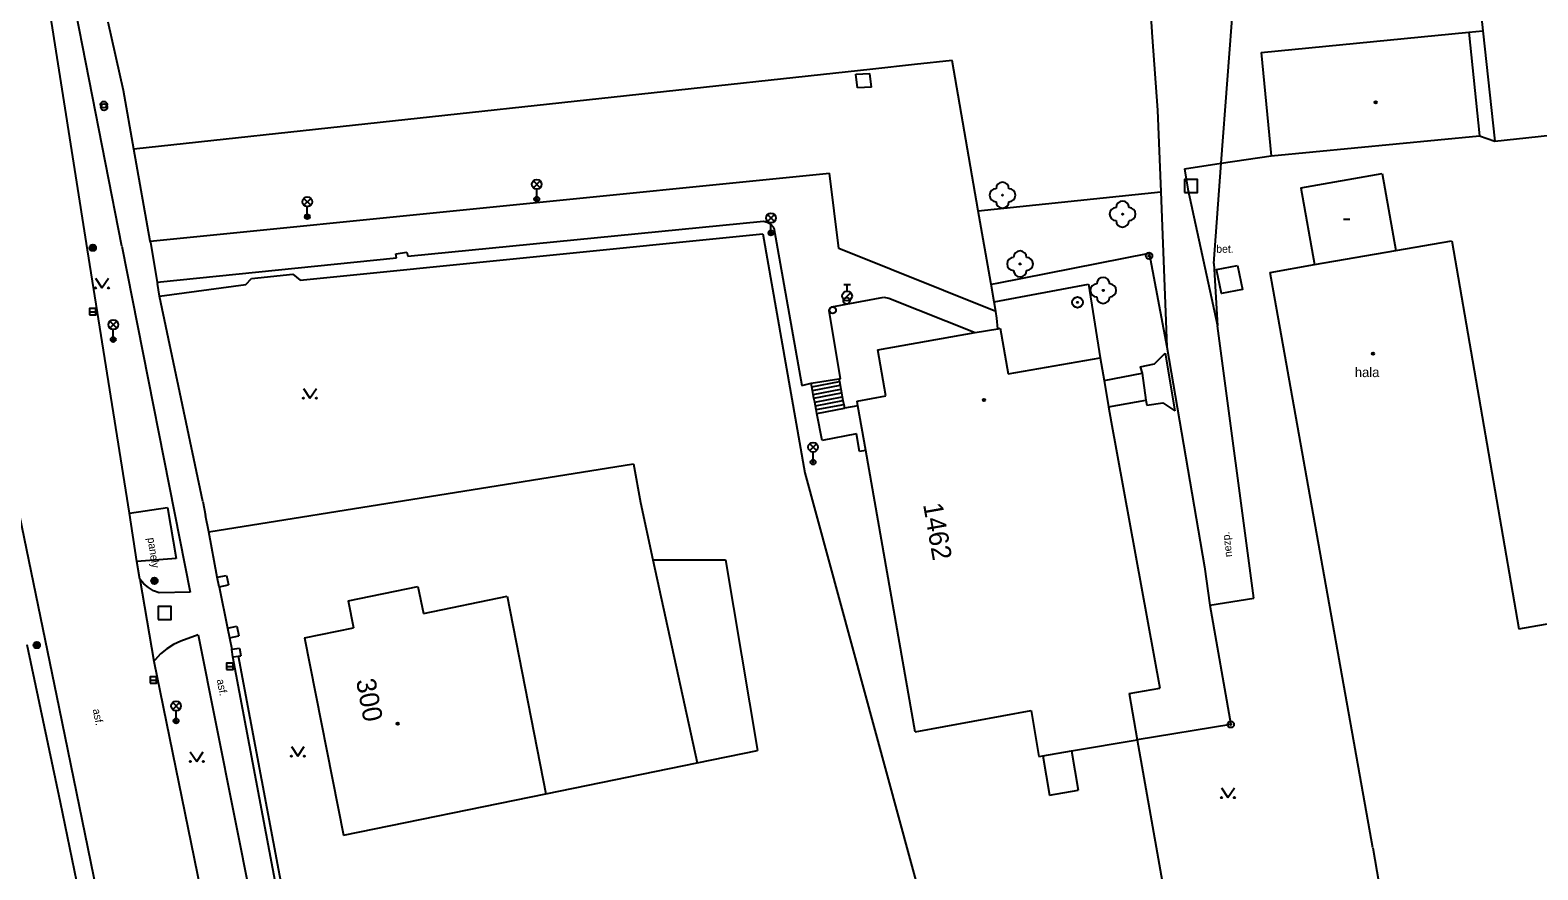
# Model space of a CAD drawing. Extents: x -640201 to -639641, y -1044739 to -1044317.
# Drawn here: x -640104 to -639987.9, y -1044553.8 to -1044489 of the extents above; entities that cross this region are included whole.
import ezdxf

# ---------------------------------------------------------------- set-up
doc = ezdxf.new("R2010")
doc.units = 0
for name, color, linetype in [('Budovy', 7, 'Continuous'), ('Ploty', 7, 'Continuous'), ('Pol_bod_pole', 7, 'Continuous'), ('Popis objektů', 7, 'Continuous'), ('Popis povrchů', 7, 'Continuous'), ('Popis ČP_ ČE', 7, 'Continuous'), ('Rozhraní ploch 1', 7, 'Continuous'), ('Rozhraní ploch 2', 7, 'Continuous'), ('Sloupy_označník', 7, 'Continuous'), ('Vstup na pozemky', 7, 'Continuous'), ('Zeleň - stromy', 7, 'Continuous'), ('Znaky doprava', 7, 'Continuous'), ('Znaky kanalizace', 7, 'Continuous'), ('Znaky voda', 7, 'Continuous'), ('Značky KM', 7, 'Continuous'), ('Značky předmětů', 7, 'Continuous'), ('Šachty ner_', 7, 'Continuous')]:
    doc.layers.add(name, color=color, linetype=linetype)

msp = doc.modelspace()

# ---------------------------------------------------------------- linework, layer by layer
at = {"layer": 'Budovy'}
for p, q in [((-639993.46, -1044476.5), (-639992.1, -1044489.08)), ((-639992.1, -1044489.08), (-639991.18, -1044497.58)), ((-640009.17, -1044490.73), (-640008.41, -1044498.7)), ((-639991.18, -1044497.58), (-639972.81, -1044495.6)), ((-640008.41, -1044498.7), (-639992.37, -1044497.17)), ((-639998.802, -1044506.013), (-639994.48, -1044505.27)), ((-639994.48, -1044505.27), (-639989.34, -1044535.18)), ((-640005.07, -1044507.09), (-639998.802, -1044506.013)), ((-640008.48, -1044507.7), (-640005.07, -1044507.09)), ((-640000.58, -1044552.05), (-640008.48, -1044507.7)), ((-640038.72, -1044513.66), (-640031.213, -1044512.337)), ((-640031.213, -1044512.337), (-640029.48, -1044512.032)), ((-640029.48, -1044512.032), (-640029.3, -1044512)), ((-640029.3, -1044512), (-640028.681, -1044515.512)), ((-640038.1, -1044517.21), (-640038.72, -1044513.66)), ((-640028.681, -1044515.512), (-640021.59, -1044514.29)), ((-640021.59, -1044514.29), (-640021.289, -1044516.036)), ((-640021.289, -1044516.036), (-640020.941, -1044518.057)), ((-640040.31, -1044517.62), (-640038.1, -1044517.21)), ((-640040.247, -1044517.977), (-640040.31, -1044517.62)), ((-640039.643, -1044521.416), (-640040.247, -1044517.977)), ((-640020.941, -1044518.057), (-640020.741, -1044519.217)), ((-640020.741, -1044519.217), (-640017, -1044539.74)), ((-640035.83, -1044543.11), (-640039.643, -1044521.416)), ((-640079.53, -1044533.01), (-640074.16, -1044531.92)), ((-640074.16, -1044531.92), (-640073.73, -1044533.98)), ((-640079.53, -1044533.01), (-640079.1, -1044535.09)), ((-640073.73, -1044533.98), (-640067.26, -1044532.65)), ((-640067.26, -1044532.65), (-640064.29, -1044547.9)), ((-639989.34, -1044535.18), (-639974.71, -1044532.58)), ((-640082.899, -1044535.853), (-640079.1, -1044535.09)), ((-640082.899, -1044535.853), (-640079.882, -1044551.091)), ((-640019.36, -1044540.15), (-640017, -1044539.74)), ((-640019.36, -1044540.15), (-640018.74, -1044543.72)), ((-640035.83, -1044543.11), (-640026.91, -1044541.48)), ((-640026.91, -1044541.48), (-640026.3, -1044545.01)), ((-640023.8, -1044544.58), (-640018.74, -1044543.72)), ((-640026.3, -1044545.01), (-640026.01, -1044544.96)), ((-640026.01, -1044544.96), (-640023.8, -1044544.58)), ((-640079.882, -1044551.091), (-640064.29, -1044547.9)), ((-640000.58, -1044552.05), (-639995.38, -1044582.15))]:
    msp.add_line(p, q, dxfattribs=at)
at = {"layer": 'Ploty'}
for p, q in [((-640032.99, -1044491.36), (-640035.9, -1044491.67)), ((-640030.975, -1044502.956), (-640032.99, -1044491.36)), ((-640039.11, -1044492.03), (-640096.034, -1044498.198)), ((-640096.034, -1044498.198), (-640096.84, -1044493.68)), ((-640094.771, -1044505.283), (-640096.034, -1044498.198)), ((-640030.015, -1044508.48), (-640030.975, -1044502.956)), ((-640094.75, -1044505.4), (-640094.771, -1044505.283)), ((-640083.21, -1044508.28), (-640047.58, -1044504.72)), ((-640047.58, -1044504.72), (-640044.35, -1044523.14)), ((-640029.53, -1044508.51), (-640017.82, -1044506.21)), ((-640017.82, -1044506.21), (-640016.46, -1044513.44)), ((-640086.97, -1044508.15), (-640083.78, -1044507.82)), ((-640083.78, -1044507.82), (-640083.21, -1044508.28)), ((-640094.05, -1044509.525), (-640094.22, -1044508.54)), ((-640094.05, -1044509.525), (-640087.4, -1044508.62)), ((-640087.4, -1044508.62), (-640086.97, -1044508.15)), ((-640029.994, -1044508.601), (-640029.53, -1044508.51)), ((-640090.716, -1044525.35), (-640094.05, -1044509.525)), ((-640016.46, -1044513.44), (-640013.56, -1044530.38)), ((-640090.266, -1044527.687), (-640057.55, -1044522.46)), ((-640044.35, -1044523.14), (-640035.04, -1044557.34)), ((-640089.613, -1044531.2), (-640088.886, -1044531.063)), ((-640088.886, -1044531.063), (-640088.738, -1044531.772)), ((-640089.462, -1044531.923), (-640089.613, -1044531.2)), ((-640089.462, -1044531.923), (-640088.738, -1044531.772)), ((-640088.822, -1044535.129), (-640088.098, -1044534.978)), ((-640088.669, -1044535.864), (-640087.945, -1044535.713)), ((-640088.098, -1044534.978), (-640087.945, -1044535.713)), ((-640088.397, -1044537.337), (-640088.489, -1044536.753)), ((-640087.896, -1044536.66), (-640087.804, -1044537.244)), ((-640083.755, -1044561.923), (-640088.397, -1044537.337)), ((-640083.438, -1044561.392), (-640087.971, -1044537.27))]:
    msp.add_line(p, q, dxfattribs=at)
for points in [[(-640029.54, -1044511.21), (-640029.629, -1044510.701), (-640029.76, -1044509.949), (-640029.994, -1044508.601), (-640030.015, -1044508.48)], [(-640089.613, -1044531.2), (-640090.266, -1044527.687), (-640090.508, -1044526.43)], [(-640088.489, -1044536.753), (-640088.475, -1044536.751), (-640087.896, -1044536.66)], [(-640088.397, -1044537.337), (-640087.971, -1044537.27), (-640087.804, -1044537.244)]]:
    msp.add_lwpolyline(points, dxfattribs=at)
at = {"layer": 'Pol_bod_pole'}
for radius in [0.412, 0.05]:
    msp.add_circle((-640023.33, -1044510), radius, dxfattribs=at)
at = {"layer": 'Rozhraní ploch 1'}
for p, q in [((-640101.774, -1044541.352), (-640127.52, -1044416.154)), ((-640096.96, -1044505.67), (-640108.98, -1044444.45)), ((-640099.61, -1044505.95), (-640103.4, -1044481.78)), ((-640094.771, -1044505.283), (-640042.43, -1044500.05)), ((-640041.72, -1044505.86), (-640042.43, -1044500.05)), ((-640074.92, -1044506.45), (-640047.52, -1044503.74)), ((-640046.72, -1044504.26), (-640044.56, -1044516.4)), ((-640096.376, -1044526.243), (-640099.61, -1044505.95)), ((-640096.96, -1044505.67), (-640091.701, -1044532.356)), ((-640094.237, -1044508.439), (-640075.808, -1044506.574)), ((-640075.84, -1044506.26), (-640075.01, -1044506.14)), ((-640075.808, -1044506.574), (-640075.84, -1044506.26)), ((-640075.01, -1044506.14), (-640074.92, -1044506.45)), ((-640029.629, -1044510.701), (-640041.72, -1044505.86)), ((-640042.25, -1044510.36), (-640038.24, -1044509.61)), ((-640038.24, -1044509.61), (-640037.86, -1044509.67)), ((-640037.86, -1044509.67), (-640031.213, -1044512.337)), ((-640042.47, -1044510.63), (-640042.39, -1044510.45)), ((-640041.58, -1044515.9), (-640042.47, -1044510.63)), ((-640042.39, -1044510.45), (-640042.25, -1044510.36)), ((-640041.71, -1044515.91), (-640041.58, -1044515.9)), ((-640044.56, -1044516.4), (-640043.86, -1044516.22)), ((-640095.572, -1044531.33), (-640094.49, -1044537.672)), ((-640091.701, -1044532.356), (-640094.082, -1044532.398)), ((-640091.068, -1044535.637), (-640092.413, -1044536.116)), ((-640091.068, -1044535.637), (-640080.81, -1044587.362)), ((-640104.281, -1044536.382), (-640101.71, -1044548.529)), ((-640094.49, -1044537.672), (-640084.439, -1044586.944)), ((-640089.489, -1044600.951), (-640101.774, -1044541.352)), ((-640101.71, -1044548.529), (-640090.9, -1044601.282))]:
    msp.add_line(p, q, dxfattribs=at)
for points in [[(-640047.52, -1044503.74), (-640047.237, -1044503.813), (-640046.984, -1044503.96), (-640046.78, -1044504.169), (-640046.72, -1044504.26)], [(-640011, -1044507.17), (-640010.62, -1044509), (-640012.24, -1044509.31), (-640012.62, -1044507.48), (-640011, -1044507.17)], [(-640095.572, -1044531.33), (-640095.799, -1044529.973), (-640096.376, -1044526.243)], [(-640094.082, -1044532.398), (-640094.517, -1044532.233), (-640094.917, -1044531.996), (-640095.27, -1044531.695), (-640095.572, -1044531.33)], [(-640092.413, -1044536.116), (-640092.974, -1044536.375), (-640093.496, -1044536.703), (-640093.972, -1044537.097), (-640094.393, -1044537.549), (-640094.49, -1044537.672)]]:
    msp.add_lwpolyline(points, dxfattribs=at)
at = {"layer": 'Rozhraní ploch 2'}
for p, q in [((-640012.26, -1044499.28), (-640010.58, -1044477.15)), ((-640017.95, -1044483.55), (-640017.59, -1044489.55)), ((-640009.17, -1044490.73), (-639993.18, -1044489.18)), ((-639993.18, -1044489.18), (-639992.1, -1044489.08)), ((-639993.18, -1044489.18), (-639992.37, -1044497.17)), ((-640017.59, -1044489.55), (-640017.16, -1044495.19)), ((-640040.41, -1044492.41), (-640039.32, -1044492.35)), ((-640040.29, -1044493.47), (-640040.41, -1044492.41)), ((-640039.2, -1044493.41), (-640039.32, -1044492.35)), ((-640039.2, -1044493.41), (-640040.29, -1044493.47)), ((-640017.16, -1044495.19), (-640016.919, -1044501.471)), ((-639992.37, -1044497.17), (-639991.18, -1044497.58)), ((-640015.1, -1044499.7), (-640012.26, -1044499.28)), ((-640015.1, -1044499.7), (-640014.82, -1044501.27)), ((-640012.84, -1044507.01), (-640012.26, -1044499.28)), ((-640012.26, -1044499.28), (-640008.41, -1044498.7)), ((-640006.12, -1044501.18), (-639999.87, -1044500.07)), ((-639999.87, -1044500.07), (-639998.802, -1044506.013)), ((-640030.975, -1044502.956), (-640016.919, -1044501.471)), ((-640016.919, -1044501.471), (-640016.46, -1044513.44)), ((-640014.82, -1044501.27), (-640012.54, -1044511.8)), ((-640006.12, -1044501.18), (-640005.07, -1044507.09)), ((-640012.84, -1044507.01), (-640012.54, -1044511.8)), ((-640029.76, -1044509.949), (-640022.49, -1044508.6)), ((-640022.49, -1044508.6), (-640021.59, -1044514.29)), ((-640009.74, -1044532.82), (-640012.54, -1044511.8)), ((-640018.5, -1044514.97), (-640017.39, -1044514.74)), ((-640017.39, -1044514.74), (-640016.58, -1044513.93)), ((-640016.58, -1044513.93), (-640015.84, -1044518.37)), ((-640043.86, -1044516.22), (-640041.71, -1044515.91)), ((-640021.289, -1044516.036), (-640018.36, -1044515.47)), ((-640018.5, -1044514.97), (-640018.36, -1044515.47)), ((-640018.36, -1044515.47), (-640018.06, -1044517.53)), ((-640043.804, -1044516.508), (-640041.675, -1044516.095)), ((-640043.747, -1044516.803), (-640041.62, -1044516.39)), ((-640043.69, -1044517.097), (-640041.565, -1044516.685)), ((-640043.633, -1044517.392), (-640041.51, -1044516.98)), ((-640043.576, -1044517.686), (-640041.455, -1044517.275)), ((-640043.519, -1044517.981), (-640041.4, -1044517.57)), ((-640043.462, -1044518.275), (-640041.345, -1044517.865)), ((-640043.405, -1044518.57), (-640041.29, -1044518.16)), ((-640040.247, -1044517.977), (-640041.29, -1044518.16)), ((-640020.941, -1044518.057), (-640018.06, -1044517.53)), ((-640018.06, -1044517.53), (-640018, -1044517.92)), ((-640018, -1044517.92), (-640016.77, -1044517.76)), ((-640016.77, -1044517.76), (-640015.84, -1044518.37)), ((-640040.36, -1044520.15), (-640043, -1044520.66)), ((-640040.12, -1044521.5), (-640040.36, -1044520.15)), ((-640039.643, -1044521.416), (-640040.12, -1044521.5)), ((-640057.55, -1044522.46), (-640056.99, -1044525.44)), ((-640096.376, -1044526.243), (-640093.441, -1044525.817)), ((-640093.441, -1044525.817), (-640092.762, -1044529.745)), ((-640056.99, -1044525.44), (-640056.04, -1044529.84)), ((-640092.762, -1044529.745), (-640095.799, -1044529.973)), ((-640056.04, -1044529.84), (-640050.45, -1044529.85)), ((-640056.04, -1044529.84), (-640052.64, -1044545.51)), ((-640050.45, -1044529.85), (-640047.99, -1044544.56)), ((-640013.56, -1044530.38), (-640013.13, -1044533.34)), ((-640013.13, -1044533.34), (-640009.74, -1044532.82)), ((-640013.13, -1044533.34), (-640011.53, -1044542.54)), ((-640011.53, -1044542.54), (-640018.74, -1044543.72)), ((-640018.74, -1044543.72), (-640016.53, -1044556.23)), ((-640052.64, -1044545.51), (-640047.99, -1044544.56)), ((-640026.01, -1044544.96), (-640025.49, -1044547.99)), ((-640023.8, -1044544.58), (-640023.27, -1044547.61)), ((-640064.29, -1044547.9), (-640052.64, -1044545.51)), ((-640025.49, -1044547.99), (-640023.27, -1044547.61))]:
    msp.add_line(p, q, dxfattribs=at)
for points in [[(-640041.71, -1044515.91), (-640041.675, -1044516.095), (-640041.62, -1044516.39), (-640041.565, -1044516.685), (-640041.51, -1044516.98), (-640041.455, -1044517.275), (-640041.4, -1044517.57), (-640041.345, -1044517.865), (-640041.29, -1044518.16)], [(-640043, -1044520.66), (-640043.405, -1044518.57), (-640043.462, -1044518.275), (-640043.519, -1044517.981), (-640043.576, -1044517.686), (-640043.633, -1044517.392), (-640043.69, -1044517.097), (-640043.747, -1044516.803), (-640043.804, -1044516.508), (-640043.86, -1044516.22)]]:
    msp.add_lwpolyline(points, dxfattribs=at)
at = {"layer": 'Sloupy_označník'}
for centre, radius in [((-640099.2, -1044505.79), 0.25), ((-640099.2, -1044505.79), 0.158), ((-640099.2, -1044505.79), 0.05), ((-640017.82, -1044506.42), 0.25), ((-640017.82, -1044506.42), 0.05), ((-640094.454, -1044531.476), 0.25), ((-640094.454, -1044531.476), 0.158), ((-640094.454, -1044531.476), 0.05), ((-640103.515, -1044536.425), 0.25), ((-640103.515, -1044536.425), 0.158), ((-640103.515, -1044536.425), 0.05), ((-640011.53, -1044542.54), 0.25), ((-640011.53, -1044542.54), 0.05)]:
    msp.add_circle(centre, radius, dxfattribs=at)
at = {"layer": 'Vstup na pozemky'}
for p, q in [((-640096.84, -1044493.68), (-640098.02, -1044488.4)), ((-640035.9, -1044491.67), (-640039.11, -1044492.03)), ((-640029.48, -1044512.032), (-640029.54, -1044511.21)), ((-640090.716, -1044525.35), (-640090.508, -1044526.43))]:
    msp.add_line(p, q, dxfattribs=at)
for points in [[(-640094.75, -1044505.4), (-640094.237, -1044508.439), (-640094.22, -1044508.54)], [(-640089.462, -1044531.923), (-640088.822, -1044535.129), (-640088.669, -1044535.864), (-640088.475, -1044536.751)]]:
    msp.add_lwpolyline(points, dxfattribs=at)
at = {"layer": 'Zeleň - stromy'}
for centre in [(-640029.11, -1044501.74), (-640019.86, -1044503.2), (-640027.76, -1044507.04), (-640021.35, -1044509.08)]:
    msp.add_circle(centre, 0.05, dxfattribs=at)
for centre, start, end in [((-640029.11, -1044501.24), 0, 180), ((-640029.61, -1044501.74), 90, 270), ((-640028.61, -1044501.74), 270, 90), ((-640029.11, -1044502.24), 180, 0), ((-640020.36, -1044503.2), 90, 270), ((-640019.86, -1044502.7), 0, 180), ((-640019.36, -1044503.2), 270, 90), ((-640019.86, -1044503.7), 180, 0), ((-640028.26, -1044507.04), 90, 270), ((-640027.76, -1044506.54), 0, 180), ((-640027.26, -1044507.04), 270, 90), ((-640027.76, -1044507.54), 180, 0), ((-640021.85, -1044509.08), 90, 270), ((-640021.35, -1044508.58), 0, 180), ((-640020.85, -1044509.08), 270, 90), ((-640021.35, -1044509.58), 180, 0)]:
    msp.add_arc(centre, 0.5, start, end, dxfattribs=at)
at = {"layer": 'Znaky doprava'}
for p, q in [((-640065.255, -1044500.635), (-640064.725, -1044501.165)), ((-640065.255, -1044501.165), (-640064.725, -1044500.635)), ((-640082.935, -1044501.985), (-640082.405, -1044502.515)), ((-640082.935, -1044502.515), (-640082.405, -1044501.985)), ((-640064.99, -1044502.05), (-640064.99, -1044501.275)), ((-640082.67, -1044503.4), (-640082.67, -1044502.625)), ((-640047.215, -1044503.235), (-640046.685, -1044503.765)), ((-640047.215, -1044503.765), (-640046.685, -1044503.235)), ((-640046.95, -1044504.65), (-640046.95, -1044503.875)), ((-640097.886, -1044511.454), (-640097.356, -1044511.984)), ((-640097.886, -1044511.984), (-640097.356, -1044511.454)), ((-640097.621, -1044512.869), (-640097.621, -1044512.094)), ((-640043.965, -1044520.905), (-640043.435, -1044521.435)), ((-640043.965, -1044521.435), (-640043.435, -1044520.905)), ((-640043.7, -1044522.32), (-640043.7, -1044521.545)), ((-640093.042, -1044540.857), (-640092.512, -1044541.387)), ((-640093.042, -1044541.387), (-640092.512, -1044540.857)), ((-640092.777, -1044542.272), (-640092.777, -1044541.497))]:
    msp.add_line(p, q, dxfattribs=at)
for centre, radius in [((-640064.99, -1044500.9), 0.375), ((-640082.67, -1044502.25), 0.375), ((-640064.99, -1044502.05), 0.19), ((-640064.99, -1044502.05), 0.05), ((-640046.95, -1044503.5), 0.375), ((-640082.67, -1044503.4), 0.19), ((-640082.67, -1044503.4), 0.05), ((-640046.95, -1044504.65), 0.19), ((-640046.95, -1044504.65), 0.05), ((-640097.621, -1044511.719), 0.375), ((-640097.621, -1044512.869), 0.19), ((-640097.621, -1044512.869), 0.05), ((-640043.7, -1044521.17), 0.375), ((-640043.7, -1044522.32), 0.19), ((-640043.7, -1044522.32), 0.05), ((-640092.777, -1044541.122), 0.375), ((-640092.777, -1044542.272), 0.19), ((-640092.777, -1044542.272), 0.05)]:
    msp.add_circle(centre, radius, dxfattribs=at)
at = {"layer": 'Znaky kanalizace'}
for p, q in [((-640099.457, -1044510.722), (-640098.957, -1044510.722)), ((-640094.787, -1044539.122), (-640094.287, -1044539.122)), ((-640088.886, -1044538.066), (-640088.386, -1044538.066))]:
    msp.add_line(p, q, dxfattribs=at)
for points in [[(-640099.457, -1044510.972), (-640098.957, -1044510.972), (-640098.957, -1044510.472), (-640099.457, -1044510.472)], [(-640088.886, -1044538.316), (-640088.386, -1044538.316), (-640088.386, -1044537.816), (-640088.886, -1044537.816)], [(-640094.787, -1044539.372), (-640094.287, -1044539.372), (-640094.287, -1044538.872), (-640094.787, -1044538.872)]]:
    msp.add_lwpolyline(points, close=True, dxfattribs=at)
at = {"layer": 'Znaky voda'}
for p, q in [((-640041.33, -1044508.62), (-640040.83, -1044508.62)), ((-640041.08, -1044509.145), (-640041.08, -1044508.62)), ((-640041.345, -1044509.785), (-640040.815, -1044509.255))]:
    msp.add_line(p, q, dxfattribs=at)
for centre, radius in [((-640098.35, -1044494.76), 0.25), ((-640098.33, -1044494.95), 0.25), ((-640041.08, -1044509.52), 0.375), ((-640041.12, -1044509.89), 0.25), ((-640042.19, -1044510.6), 0.25)]:
    msp.add_circle(centre, radius, dxfattribs=at)
at = {"layer": 'Značky KM'}
for p, q in [((-640098.99, -1044508.14), (-640098.49, -1044508.89)), ((-640098.49, -1044508.89), (-640097.99, -1044508.14)), ((-640082.97, -1044516.64), (-640082.47, -1044517.39)), ((-640082.47, -1044517.39), (-640081.97, -1044516.64)), ((-640091.69, -1044544.65), (-640091.19, -1044545.4)), ((-640091.19, -1044545.4), (-640090.69, -1044544.65)), ((-640083.9, -1044544.24), (-640083.4, -1044544.99)), ((-640083.4, -1044544.99), (-640082.9, -1044544.24)), ((-640012.24, -1044547.43), (-640011.74, -1044548.18)), ((-640011.74, -1044548.18), (-640011.24, -1044547.43))]:
    msp.add_line(p, q, dxfattribs=at)
for centre in [(-640098.99, -1044508.89), (-640097.99, -1044508.89), (-640082.97, -1044517.39), (-640081.97, -1044517.39), (-640083.9, -1044544.99), (-640082.9, -1044544.99), (-640091.69, -1044545.4), (-640090.69, -1044545.4), (-640012.24, -1044548.18), (-640011.24, -1044548.18)]:
    msp.add_circle(centre, 0.05, dxfattribs=at)
at = {"layer": 'Značky předmětů'}
msp.add_line((-640002.85, -1044503.59), (-640002.35, -1044503.59), dxfattribs=at)
for centre in [(-640000.35, -1044494.59), (-640000.557, -1044513.951), (-640030.54, -1044517.53), (-640075.7, -1044542.49)]:
    msp.add_circle(centre, 0.0875, dxfattribs=at)
at = {"layer": 'Šachty ner_'}
for points in [[(-640015.08, -1044501.53), (-640014.08, -1044501.53), (-640014.08, -1044500.53), (-640015.08, -1044500.53)], [(-640094.15, -1044534.44), (-640093.15, -1044534.44), (-640093.15, -1044533.44), (-640094.15, -1044533.44)]]:
    msp.add_lwpolyline(points, close=True, dxfattribs=at)

# ---------------------------------------------------------------- texts
at = {"layer": 'Popis objektů'}
msp.add_text('hala', height=0.75, dxfattribs=at).set_placement((-640001.967, -1044515.764))
at = {"layer": 'Popis povrchů'}
msp.add_text('bet.', height=0.6, dxfattribs=at).set_placement((-640012.64, -1044506.18))
for s, rotation, p in [('panely', 278.79348, (-640094.99, -1044528.178)), ('nezp.', 96.55289, (-640011.412, -1044529.61)), ('asf.', 281.21724, (-640089.655, -1044539.108)), ('asf.', 281.64711, (-640099.212, -1044541.397))]:
    msp.add_text(s, height=0.6, rotation=rotation, dxfattribs=at).set_placement(p)
at = {"layer": 'Popis ČP_ ČE'}
for s, rotation, p in [('1462', 280, (-640035.234, -1044525.585)), ('300', 280.70155, (-640078.925, -1044539.143))]:
    msp.add_text(s, height=1.5, rotation=rotation, dxfattribs=at).set_placement(p)

doc.saveas('drawing.dxf')
